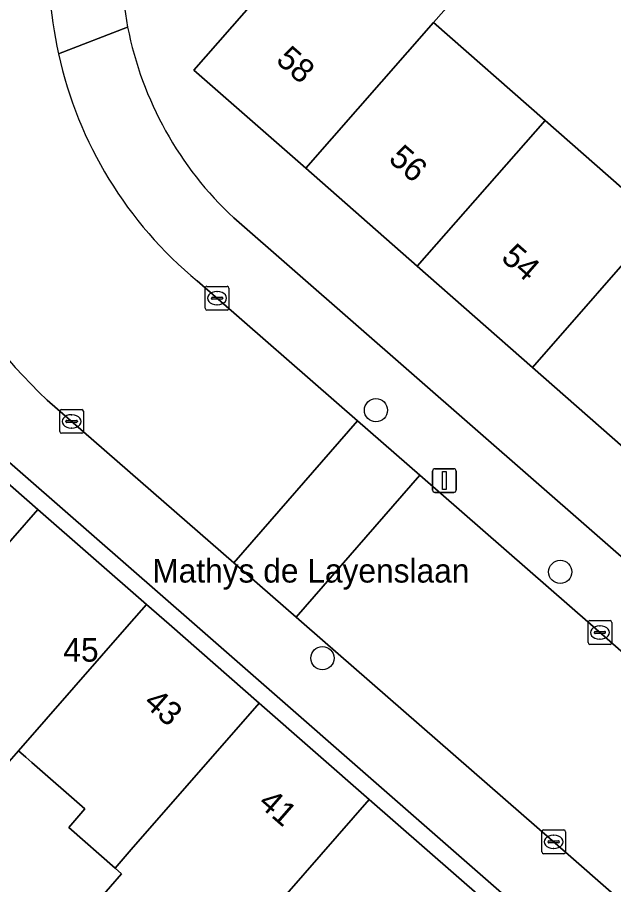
# Model space of a CAD drawing. Extents: x 160023 to 161302, y 384750 to 385707.
# Drawn here: x 160149.97 to 160175.13, y 385239.03 to 385275.59 of the extents above; entities that cross this region are included whole.
import ezdxf

# ---------------------------------------------------------------- set-up
doc = ezdxf.new("R2010")
doc.units = 0
for name, color, linetype in [('IMGEO_Boom', 7, 'Continuous'), ('IMGEO_Erf', 7, 'Continuous'), ('IMGEO_Kolk', 7, 'Continuous'), ('IMGEO_Lichtmast', 7, 'Continuous'), ('IMGEO_Openbare_ruimte_label', 7, 'Continuous'), ('IMGEO_Pand', 7, 'Continuous'), ('IMGEO_Pand_nummerreeks', 7, 'Continuous'), ('IMGEO_Rijbaan_lokaal_gesloten', 7, 'Continuous'), ('IMGEO_Rijbaan_lokaal_open', 7, 'Continuous'), ('IMGEO_Voetpad_open', 7, 'Continuous')]:
    doc.layers.add(name, color=color, linetype=linetype)

msp = doc.modelspace()

# ---------------------------------------------------------------- linework, layer by layer
at = {"layer": 'IMGEO_Boom'}
for centre in [(160165.104, 385259.028), (160172.88, 385252.211), (160162.845, 385248.574)]:
    msp.add_circle(centre, 0.489, dxfattribs=at)
at = {"layer": 'IMGEO_Erf'}
for points in [[(160169.496, 385277.611), (160167.531, 385275.372), (160172.239, 385271.243), (160177.101, 385266.977), (160179.411, 385269.609), (160184.17, 385265.434), (160188.556, 385261.586), (160186.247, 385258.954), (160186.568, 385258.673), (160194.296, 385267.521), (160195.714, 385269.592), (160194.363, 385270.502), (160193.017, 385268.502), (160189.071, 385271.16), (160190.417, 385273.159), (160173.571, 385284.757)], [(160180.818, 385252.107), (160181.176, 385252.527), (160176.468, 385256.657), (160171.709, 385260.832), (160166.847, 385265.097), (160162.139, 385269.227), (160157.419, 385273.368), (160162.676, 385279.36)], [(160147.881, 385179.757), (160153.331, 385182.894), (160161.174, 385187.582), (160161.939, 385188.142), (160164.623, 385190.524), (160170.217, 385196.478), (160169.801, 385196.926), (160176.958, 385204.861), (160180.957, 385209.509), (160179.256, 385210.996), (160181.48, 385213.538), (160183.18, 385212.051), (160185.196, 385214.261), (160184.205, 385215.122), (160189.897, 385221.607), (160189.22, 385222.221), (160157.452, 385250), (160136.269, 385268.493)], [(160159.104, 385267.131), (160176.783, 385251.691)], [(160146.189, 385258.906), (160150.84, 385254.838), (160155.416, 385250.836), (160156.372, 385250), (160160.175, 385246.674), (160164.819, 385242.612), (160169.594, 385238.436)], [(160152.967, 385237.879), (160154.373, 385239.488), (160154.1, 385239.727), (160152.141, 385241.441), (160152.822, 385242.22), (160150.589, 385244.174), (160150.33, 385244.4), (160150.022, 385244.67), (160149.332, 385243.881)]]:
    msp.add_lwpolyline(points, dxfattribs=at)
for centre, radius, start, end in [((160169.229, 385277.966), 14.87, 156.4566, 190.8082), ((160169.302, 385278.081), 14.963, 191.186, 227.0368)]:
    msp.add_arc(centre, radius, start, end, dxfattribs=at)
at = {"layer": 'IMGEO_Kolk'}
for p, q in [((160157.899, 385263.323), (160157.899, 385264.175)), ((160157.974, 385264.249), (160158.826, 385264.249)), ((160158.387, 385264.029), (160158.412, 385264.029)), ((160158.9, 385264.175), (160158.9, 385263.323)), ((160158.158, 385263.743), (160158.158, 385263.755)), ((160158.596, 385263.706), (160158.198, 385263.706)), ((160158.201, 385263.792), (160158.599, 385263.792)), ((160158.642, 385263.755), (160158.642, 385263.743)), ((160158.826, 385263.249), (160157.974, 385263.249)), ((160158.41, 385263.469), (160158.385, 385263.469)), ((160151.761, 385258.129), (160151.761, 385258.981)), ((160151.836, 385259.055), (160152.688, 385259.055)), ((160152.249, 385258.835), (160152.274, 385258.835)), ((160152.762, 385258.981), (160152.762, 385258.129)), ((160152.02, 385258.549), (160152.02, 385258.561)), ((160152.458, 385258.512), (160152.06, 385258.512)), ((160152.063, 385258.598), (160152.461, 385258.598)), ((160152.504, 385258.561), (160152.504, 385258.549)), ((160152.272, 385258.275), (160152.247, 385258.275)), ((160152.688, 385258.055), (160151.836, 385258.055)), ((160174.054, 385249.23), (160174.054, 385250.082)), ((160174.129, 385250.156), (160174.981, 385250.156)), ((160175.055, 385250.082), (160175.055, 385249.23)), ((160174.356, 385249.699), (160174.754, 385249.699)), ((160174.542, 385249.936), (160174.567, 385249.936)), ((160174.313, 385249.65), (160174.313, 385249.662)), ((160174.751, 385249.613), (160174.353, 385249.613)), ((160174.565, 385249.376), (160174.54, 385249.376)), ((160174.797, 385249.662), (160174.797, 385249.65)), ((160174.981, 385249.156), (160174.129, 385249.156)), ((160172.177, 385241.33), (160173.029, 385241.33)), ((160172.102, 385240.404), (160172.102, 385241.256)), ((160172.59, 385241.11), (160172.615, 385241.11)), ((160173.103, 385241.256), (160173.103, 385240.404)), ((160172.361, 385240.824), (160172.361, 385240.836)), ((160172.799, 385240.787), (160172.401, 385240.787)), ((160172.404, 385240.873), (160172.802, 385240.873)), ((160172.613, 385240.55), (160172.588, 385240.55)), ((160172.845, 385240.836), (160172.845, 385240.824)), ((160173.029, 385240.33), (160172.177, 385240.33))]:
    msp.add_line(p, q, dxfattribs=at)
for points in [[(160157.899, 385263.323), (160157.899, 385264.175)], [(160157.974, 385264.249), (160158.826, 385264.249)], [(160158.9, 385264.175), (160158.9, 385263.323)], [(160158.826, 385263.249), (160157.974, 385263.249)], [(160151.761, 385258.129), (160151.761, 385258.981)], [(160151.836, 385259.055), (160152.688, 385259.055)], [(160152.762, 385258.981), (160152.762, 385258.129)], [(160152.688, 385258.055), (160151.836, 385258.055)], [(160174.054, 385249.23), (160174.054, 385250.082)], [(160174.129, 385250.156), (160174.981, 385250.156)], [(160175.055, 385250.082), (160175.055, 385249.23)], [(160174.981, 385249.156), (160174.129, 385249.156)], [(160172.177, 385241.33), (160173.029, 385241.33)], [(160172.102, 385240.404), (160172.102, 385241.256)], [(160173.103, 385241.256), (160173.103, 385240.404)], [(160173.029, 385240.33), (160172.177, 385240.33)]]:
    msp.add_lwpolyline(points, dxfattribs=at)
for centre, radius, start, end in [((160157.976, 385264.173), 0.0765, 91.552, 178.448), ((160157.976, 385264.173), 0.0765, 91.552, 178.448), ((160158.824, 385264.173), 0.0765, 1.552, 88.448), ((160158.824, 385264.173), 0.0765, 1.552, 88.448), ((160158.198, 385263.752), 0.0403, 85.8775, 175.7526), ((160158.195, 385263.742), 0.0366, 178.938, 274.7102), ((160158.599, 385263.749), 0.043, 264.8664, 352.4533), ((160158.603, 385263.754), 0.0386, 1.7309, 96.639), ((160157.976, 385263.325), 0.0765, 181.552, 268.448), ((160157.976, 385263.325), 0.0765, 181.552, 268.448), ((160158.824, 385263.325), 0.0765, 271.552, 358.448), ((160158.824, 385263.325), 0.0765, 271.552, 358.448), ((160151.838, 385258.979), 0.0765, 91.552, 178.448), ((160151.838, 385258.979), 0.0765, 91.552, 178.448), ((160152.686, 385258.979), 0.0765, 1.552, 88.448), ((160152.686, 385258.979), 0.0765, 1.552, 88.448), ((160152.06, 385258.558), 0.0403, 85.8775, 175.7526), ((160152.057, 385258.548), 0.0366, 178.938, 274.7102), ((160152.461, 385258.555), 0.043, 264.8664, 352.4533), ((160152.465, 385258.56), 0.0386, 1.7309, 96.639), ((160151.838, 385258.131), 0.0765, 181.552, 268.448), ((160151.838, 385258.131), 0.0765, 181.552, 268.448), ((160152.686, 385258.131), 0.0765, 271.552, 358.448), ((160152.686, 385258.131), 0.0765, 271.552, 358.448), ((160174.131, 385250.08), 0.0765, 91.552, 178.448), ((160174.131, 385250.08), 0.0765, 91.552, 178.448), ((160174.979, 385250.08), 0.0765, 1.552, 88.448), ((160174.979, 385250.08), 0.0765, 1.552, 88.448), ((160174.353, 385249.659), 0.0403, 85.8775, 175.7526), ((160174.758, 385249.661), 0.0386, 1.7309, 96.639), ((160174.35, 385249.649), 0.0366, 178.938, 274.7102), ((160174.754, 385249.656), 0.043, 264.8664, 352.4533), ((160174.131, 385249.232), 0.0765, 181.552, 268.448), ((160174.131, 385249.232), 0.0765, 181.552, 268.448), ((160174.979, 385249.232), 0.0765, 271.552, 358.448), ((160174.979, 385249.232), 0.0765, 271.552, 358.448), ((160172.179, 385241.254), 0.0765, 91.552, 178.448), ((160172.179, 385241.254), 0.0765, 91.552, 178.448), ((160173.027, 385241.254), 0.0765, 1.552, 88.448), ((160173.027, 385241.254), 0.0765, 1.552, 88.448), ((160172.401, 385240.833), 0.0403, 85.8775, 175.7526), ((160172.398, 385240.823), 0.0366, 178.938, 274.7102), ((160172.802, 385240.83), 0.043, 264.8664, 352.4533), ((160172.806, 385240.835), 0.0386, 1.7309, 96.639), ((160172.179, 385240.406), 0.0765, 181.552, 268.448), ((160172.179, 385240.406), 0.0765, 181.552, 268.448), ((160173.027, 385240.406), 0.0765, 271.552, 358.448), ((160173.027, 385240.406), 0.0765, 271.552, 358.448)]:
    msp.add_arc(centre, radius, start, end, dxfattribs=at)
for centre, major_axis, ratio, start_param, end_param in [((160158.386, 385263.749), (-0.387, 0.002), 0.722429, 4.712389, 7.853982), ((160158.411, 385263.749), (-0.39, 0.002), 0.717154, 1.570796, 4.712389), ((160152.248, 385258.555), (-0.387, 0.002), 0.722429, 4.712389, 7.853982), ((160152.273, 385258.555), (-0.39, 0.002), 0.717154, 1.570796, 4.712389), ((160174.541, 385249.656), (-0.387, 0.002), 0.722429, 4.712389, 7.853982), ((160174.566, 385249.656), (-0.39, 0.002), 0.717154, 1.570796, 4.712389), ((160172.589, 385240.83), (-0.387, 0.002), 0.722429, 4.712389, 7.853982), ((160172.614, 385240.83), (-0.39, 0.002), 0.717154, 1.570796, 4.712389)]:
    msp.add_ellipse(centre, major_axis=major_axis, ratio=ratio, start_param=start_param, end_param=end_param, dxfattribs=at)
at = {"layer": 'IMGEO_Lichtmast'}
for p, q in [((160167.494, 385255.662), (160167.494, 385256.462)), ((160167.494, 385256.462), (160167.494, 385255.662)), ((160167.594, 385256.562), (160168.384, 385256.562)), ((160168.384, 385256.562), (160167.594, 385256.562)), ((160168.484, 385256.462), (160168.484, 385255.662)), ((160168.484, 385255.662), (160168.484, 385256.462)), ((160168.384, 385255.562), (160167.594, 385255.562)), ((160167.594, 385255.562), (160168.384, 385255.562))]:
    msp.add_line(p, q, dxfattribs=at)
msp.add_lwpolyline([(160167.914, 385256.437), (160168.064, 385256.437), (160168.064, 385255.687), (160167.914, 385255.687), (160167.914, 385256.437)], dxfattribs=at)
for centre, start, end in [((160167.594, 385256.462), 90, 180), ((160167.594, 385256.462), 90, 180), ((160168.384, 385256.462), 0, 90), ((160168.384, 385256.462), 360, 90), ((160167.594, 385255.662), 180, 270), ((160167.594, 385255.662), 180, 270), ((160168.384, 385255.662), 270, 0), ((160168.384, 385255.662), 270, 0)]:
    msp.add_arc(centre, 0.1, start, end, dxfattribs=at)
at = {"layer": 'IMGEO_Pand'}
for points in [[(160166.609, 385280.144), (160167.959, 385283.423), (160166.648, 385283.994), (160162.064, 385285.991), (160160.143, 385281.583), (160162.676, 385279.36), (160157.419, 385273.368), (160162.139, 385269.227), (160167.531, 385275.372), (160169.496, 385277.611)], [(160162.139, 385269.227), (160166.847, 385265.097), (160172.239, 385271.243), (160167.531, 385275.372)], [(160166.847, 385265.097), (160171.709, 385260.832), (160177.101, 385266.977), (160172.239, 385271.243)], [(160184.17, 385265.434), (160179.411, 385269.609), (160177.101, 385266.977), (160171.709, 385260.832), (160176.468, 385256.657)], [(160150.84, 385254.838), (160146.189, 385258.906), (160140.817, 385252.763), (160143.426, 385250.48), (160143.007, 385250), (160142.72, 385249.672), (160144.761, 385247.888), (160145.444, 385248.669), (160146.608, 385250)], [(160155.416, 385250.836), (160150.84, 385254.838), (160146.608, 385250), (160145.444, 385248.669), (160145.609, 385248.524), (160146.442, 385247.795), (160148.164, 385246.29), (160147.477, 385245.504), (160149.332, 385243.881), (160150.022, 385244.67), (160154.685, 385250)], [(160160.175, 385246.674), (160156.372, 385250), (160155.416, 385250.836), (160154.685, 385250), (160150.022, 385244.67), (160150.33, 385244.4), (160150.589, 385244.174), (160152.822, 385242.22), (160152.141, 385241.441), (160154.1, 385239.727), (160154.779, 385240.503)], [(160164.819, 385242.612), (160160.175, 385246.674), (160154.779, 385240.503), (160154.1, 385239.727), (160154.373, 385239.488), (160152.967, 385237.879), (160157.336, 385234.058), (160158.756, 385235.681), (160159.314, 385236.319)], [(160169.594, 385238.436), (160164.819, 385242.612), (160159.314, 385236.319), (160158.756, 385235.681), (160161.109, 385233.623), (160159.467, 385231.735), (160159.284, 385230.398), (160161.143, 385228.772), (160164.207, 385232.276)]]:
    msp.add_lwpolyline(points, close=True, dxfattribs=at)
at = {"layer": 'IMGEO_Rijbaan_lokaal_gesloten'}
msp.add_lwpolyline([(160151.23, 385259.454), (160159.103, 385252.594), (160164.321, 385258.583), (160157.565, 385264.477)], dxfattribs=at)
msp.add_lwpolyline([(160201.656, 385215.712), (160206.637, 385221.839), (160202.411, 385225.421), (160198.24, 385229.032), (160193.527, 385233.12), (160188.548, 385237.492), (160175.917, 385248.467), (160174.16, 385250), (160166.952, 385256.288), (160161.735, 385250.3), (160162.08, 385250), (160173.333, 385240.195), (160191.374, 385224.407), (160193.713, 385222.293), (160198.237, 385218.491)], close=True, dxfattribs=at)
for centre, radius, start, end in [((160168.331, 385277.827), 17.045, 157.2994, 192.8127), ((160168.48, 385277.731), 17.17, 192.3899, 230.5273), ((160168.728, 385277.843), 25.384, 191.7936, 226.4224)]:
    msp.add_arc(centre, radius, start, end, dxfattribs=at)
at = {"layer": 'IMGEO_Rijbaan_lokaal_open'}
msp.add_lwpolyline([(160161.735, 385250.3), (160166.952, 385256.288), (160164.321, 385258.583), (160159.103, 385252.594)], close=True, dxfattribs=at)
at = {"layer": 'IMGEO_Voetpad_open'}
for points in [[(160151.71, 385274.047), (160154.623, 385275.178)], [(160154.623, 385275.178), (160151.71, 385274.047)], [(160136.269, 385268.493), (160157.452, 385250), (160189.22, 385222.221), (160189.897, 385221.607), (160192.368, 385219.549), (160192.997, 385220.266), (160193.416, 385220.739), (160193.018, 385221.086), (160193.214, 385221.318), (160192.998, 385221.497), (160193.713, 385222.293), (160191.374, 385224.407), (160173.333, 385240.195)], [(160180.187, 385247.054), (160176.783, 385251.691), (160159.104, 385267.131)], [(160157.565, 385264.477), (160164.321, 385258.583), (160166.952, 385256.288), (160174.16, 385250), (160175.917, 385248.467)], [(160173.333, 385240.195), (160162.08, 385250), (160161.735, 385250.3), (160159.103, 385252.594), (160151.23, 385259.454)]]:
    msp.add_lwpolyline(points, dxfattribs=at)
for centre, radius, start, end in [((160168.331, 385277.827), 17.045, 157.2994, 192.8127), ((160169.229, 385277.966), 14.87, 156.4566, 190.8082), ((160169.302, 385278.081), 14.963, 191.186, 227.0368), ((160168.48, 385277.731), 17.17, 192.3899, 230.5273), ((160168.728, 385277.843), 25.384, 191.7936, 226.4224)]:
    msp.add_arc(centre, radius, start, end, dxfattribs=at)

# ---------------------------------------------------------------- texts
at = {"layer": 'IMGEO_Openbare_ruimte_label'}
msp.add_text('Mathys de Layenslaan', height=1, dxfattribs=at).set_placement((160155.666, 385251.761))
at = {"layer": 'IMGEO_Pand_nummerreeks'}
for s, rotation, p in [('58', 318.7413, (160160.838, 385273.722)), ('56', 318.7409, (160165.588, 385269.556)), ('54', 318.7409, (160170.339, 385265.388)), ('43', 318.8273, (160155.251, 385246.624)), ('41', 318.8273, (160160.085, 385242.395))]:
    msp.add_text(s, height=1, rotation=rotation, dxfattribs=at).set_placement(p)
msp.add_text('45', height=1, dxfattribs=at).set_placement((160151.912, 385248.426))

doc.saveas('drawing.dxf')
